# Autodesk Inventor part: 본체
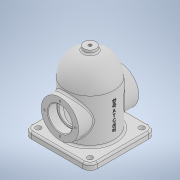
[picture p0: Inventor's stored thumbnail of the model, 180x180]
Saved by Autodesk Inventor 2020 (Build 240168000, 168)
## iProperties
Created: 2021-07
Part Number: 본체
Material: 일반
Document SubType Name: Modeling
Designer: Owner
Density: 1 g/cm^3
Appearance: 기본값
Mass: 320.706 g
Surface Area: 800.755 cm^2
Volume: 320.706 cm^3
Author: Owner
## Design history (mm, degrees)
sketch "스케치1"
  geometry: C1 r 40 at (0, 0); 1 further point
  constraints: 1 centre point, 1 coincident
  dimensions: "d0" = 80 diameter of C1
extrude "돌출1" new body sketch "스케치1" distance "d1" = 124; taper "d2" = 0 deg
fillet "모깎기1" dims "d3" = 40
feature "쉘1" dims "d4" = 8
node "작업 평면1"
sketch "스케치3"
  geometry: C1 r 31 at (0, 48); 1 further point
  constraints: 1 centre point, 1 vertical alignment
  dimensions: "d6" = 62 diameter of C1; "d7" = 48 distance of point (0, 0) C1.centre
extrude "돌출2" join sketch "스케치3" stored distance "d8" = 124; taper "d9" = 0 deg
sketch "스케치4"
  geometry: C1 r 31 at (0, 0) reference; 2 further points
  constraints: 1 coincident
hole "구멍1" sketch "스케치4" at (0, 0) diameter "d10" = 33; stored, may be unused: countersink angle "d14" = 90 deg, drill point angle "d16" = 0 deg; dims "d11" = 6, "d12" = 40, "d13" = 15, "d15" = 8
sketch "스케치5"
  geometry: C1 r 31 at (0, 0) reference; 2 further points
  constraints: 1 vertical alignment
  dimensions: "d17" = 25.5 distance of C1.centre point (0, 25.5)
hole "구멍2" sketch "스케치5" at (0, 25.5) diameter "d18" = 3.242; stored, may be unused: countersink angle "d22" = 90 deg, drill point angle "d24" = 118 deg; dims "d19" = 8, "d20" = 40, "d21" = 15, "d23" = 10
node "작업 평면2"
sketch "스케치6"
  geometry: L1 (0, -40)-(0, 40) reference; 2 further points
  constraints: 1 horizontal alignment, 1 other
  dimensions: "d28" = 48 distance from line of L1 point (48, 0)
feature "엠보싱1" sketch "스케치6" dims "d1" = 124, "d2" = 0, "d29" = 0.5, "d30" = 0
sketch "스케치7"
  geometry: L1 (-55, -55)-(55, -55); L2 (55, -55)-(55, 55); L3 (55, 55)-(-55, 55); L4 (-55, 55)-(-55, -55); L5 (-55, -55)-(55, 55); L6 (55, -55)-(-55, 55); C1 r 40 at (0, 0) reference; 1 further point
  constraints: 12 end point, 2 midpoint, 2 parallel, 1 horizontal, 1 perpendicular
  dimensions: "d31" = 110 distance of L1.end L2.end; "d32" = 110 distance of L1.start L1.end
extrude "돌출3" join sketch "스케치7" distance "d33" = 10; taper "d34" = 0 deg
fillet "모깎기2" dims "d35" = 12
sketch "스케치8"
  geometry: A1 r 12 centre (43, -43) between (43, -55) and (55, -43) reference; 2 further points
  constraints: 1 coincident
hole "구멍3" sketch "스케치8" at (43, -43) diameter "d36" = 9; stored, may be unused: countersink angle "d40" = 90 deg, drill point angle "d42" = 118 deg; dims "d37" = 8, "d38" = 40, "d39" = 15, "d41" = 10
sketch "스케치9"
  geometry: A1 r 12 centre (-43, -43) between (-55, -43) and (-43, -55) reference; 2 further points
  constraints: 1 coincident
hole "구멍4" sketch "스케치9" at (-43, -43) diameter "d43" = 9; stored, may be unused: countersink angle "d47" = 90 deg, drill point angle "d49" = 118 deg; dims "d44" = 8, "d45" = 40, "d46" = 15, "d48" = 10
node "작업 평면3"
sketch "스케치10"
  geometry: C1 r 32 at (0, 0) reference; C2 r 10 at (0, 0); 1 further point
  constraints: 1 centre point, 1 coincident
  dimensions: "d51" = 20 diameter of C2
extrude "돌출4" join sketch "스케치10" stored distance "d52" = 10; taper "d53" = 0 deg
sketch "스케치11"
  geometry: C1 r 10 at (0, 0) reference; 2 further points
  constraints: 1 coincident
hole "구멍5" sketch "스케치11" at (0, 0) diameter "d54" = 5.1881; stored, may be unused: countersink angle "d58" = 90 deg, drill point angle "d60" = 118 deg; dims "d55" = 12, "d56" = 40, "d57" = 15, "d59" = 16
fillet "모깎기3" dims "d61" = 0.3
fillet "모깎기4" dims "d62" = 3
chamfer "모따기1" distance "d63" = 1; stored, may be unused: second distance "d64" = 2, angle "d65" = 45 deg
node "솔리드1"
pattern_circular "원형 패턴1" dims angle "d26" = 360 deg
mirror "미러1"
mirror "미러2"
feature "A9D066F2-1C7D-4E18-AEED-F7BC21143FA4" dims "d10" = 33, "d11" = 6, "d12" = 40, "d13" = 15, "d14" = 90 deg, "d15" = 8, "d16" = 0
other parameters: "d50" = 129
